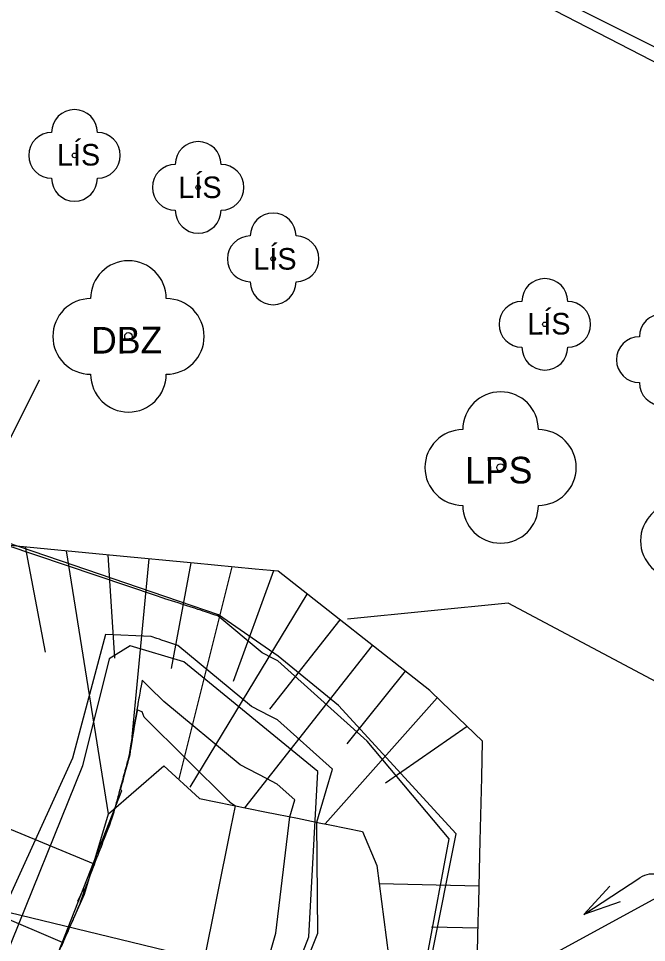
# Model space of a CAD drawing. Extents: x -564037 to -563722, y -1163561 to -1163412.
# Drawn here: x -563889.78 to -563870.9, y -1163493.12 to -1163465.35 of the extents above; entities that cross this region are included whole.
import ezdxf

# ---------------------------------------------------------------- set-up
doc = ezdxf.new("R2010")
doc.units = 0
for name, color, linetype in [('5', 7, 'Continuous'), ('Default', 7, 'Continuous'), ('Line', 7, 'Continuous'), ('Obvod PU', 7, 'Continuous'), ('podélný profil', 7, 'Continuous'), ('Vrstva 1', 7, 'Continuous'), ('Vrstva 2', 7, 'Continuous')]:
    doc.layers.add(name, color=color, linetype=linetype)

msp = doc.modelspace()

# ---------------------------------------------------------------- linework, layer by layer
msp.add_line((-563887.997, -1163491.869), (-563887.811, -1163491.492))
for points in [[(-563982.839, -1163488.47), (-563983.409, -1163491.846), (-563990.891, -1163500.051), (-563993.495, -1163501.54), (-564001.695, -1163505.76), (-564021.072, -1163514.028), (-564021.939, -1163519.359), (-564028.021, -1163535.92), (-563982.332, -1163543.556), (-563870.708, -1163549.442), (-563829.278, -1163493.346), (-563857.264, -1163473.56), (-563873.956, -1163464.96), (-563885.354, -1163462.845), (-563964.187, -1163417.135), (-563977.612, -1163460.096), (-563977.509, -1163470.055), (-563981.031, -1163479.642), (-563982.839, -1163488.47)], [(-563890.966, -1163479.851), (-563889.152, -1163476.21), (-563889.15, -1163476.207)], [(-563878.137, -1163496.97), (-563876.837, -1163490), (-563879.296, -1163487.066), (-563881.987, -1163484.651), (-563882.119, -1163484.582), (-563882.455, -1163484.408), (-563883.788, -1163483.304), (-563883.864, -1163483.279), (-563884.159, -1163483.181), (-563884.226, -1163483.159), (-563884.302, -1163483.134), (-563884.34, -1163483.121), (-563884.386, -1163483.106), (-563884.482, -1163483.074), (-563884.592, -1163483.038), (-563884.718, -1163482.996), (-563884.865, -1163482.947), (-563884.978, -1163482.91), (-563885.376, -1163482.786), (-563885.4, -1163482.777), (-563885.486, -1163482.747), (-563885.596, -1163482.707), (-563890.151, -1163481.173)], [(-563866.782, -1163487.32), (-563875.054, -1163482.917), (-563879.887, -1163483.398)], [(-563882.19, -1163496.364), (-563880.778, -1163492.835), (-563880.808, -1163489.502), (-563880.527, -1163488.546), (-563880.34, -1163487.91), (-563881.995, -1163486.424), (-563882.215, -1163486.31), (-563882.772, -1163486.021), (-563884.984, -1163484.19), (-563885.111, -1163484.148), (-563885.233, -1163484.108), (-563885.348, -1163484.069), (-563885.478, -1163484.026), (-563885.544, -1163484.004), (-563885.623, -1163483.978), (-563885.788, -1163483.923), (-563887.164, -1163483.863), (-563888.153, -1163487.579), (-563890.867, -1163493.518)], [(-563883.008, -1163496.199), (-563882.04, -1163492.836), (-563881.625, -1163489.337), (-563881.476, -1163488.829), (-563882.005, -1163488.354), (-563882.32, -1163488.191), (-563883.117, -1163487.777), (-563885.412, -1163485.878), (-563885.848, -1163485.443), (-563886.064, -1163485.228), (-563886.076, -1163485.297), (-563886.076, -1163485.299), (-563886.085, -1163485.349), (-563886.086, -1163485.357), (-563886.119, -1163485.544), (-563886.123, -1163485.565), (-563886.154, -1163485.739), (-563886.159, -1163485.771), (-563886.188, -1163485.934), (-563886.195, -1163485.977), (-563886.222, -1163486.129), (-563886.225, -1163486.143), (-563886.233, -1163486.193), (-563886.255, -1163486.313), (-563886.255, -1163486.317), (-563886.275, -1163486.425), (-563886.283, -1163486.475), (-563886.288, -1163486.503), (-563886.291, -1163486.518), (-563886.312, -1163486.636), (-563886.324, -1163486.708), (-563886.339, -1163486.796), (-563886.352, -1163486.873), (-563886.356, -1163486.898), (-563886.367, -1163486.965), (-563886.38, -1163487.043), (-563886.387, -1163487.088), (-563886.417, -1163487.278), (-563886.42, -1163487.295), (-563886.422, -1163487.306), (-563886.427, -1163487.341), (-563886.437, -1163487.403), (-563886.447, -1163487.469), (-563886.478, -1163487.59), (-563886.495, -1163487.654), (-563886.499, -1163487.669), (-563886.517, -1163487.732), (-563886.546, -1163487.835), (-563886.579, -1163487.957), (-563886.595, -1163488.016), (-563886.628, -1163488.14), (-563886.644, -1163488.198), (-563886.656, -1163488.242), (-563886.661, -1163488.262), (-563886.683, -1163488.343), (-563886.693, -1163488.379), (-563886.719, -1163488.477), (-563886.73, -1163488.518), (-563886.738, -1163488.548), (-563886.742, -1163488.561), (-563886.761, -1163488.632), (-563886.775, -1163488.684), (-563886.791, -1163488.742), (-563886.826, -1163488.871), (-563886.84, -1163488.923), (-563886.875, -1163489.052), (-563886.889, -1163489.104), (-563886.908, -1163489.177), (-563886.916, -1163489.206), (-563886.923, -1163489.229), (-563886.938, -1163489.287), (-563886.982, -1163489.414), (-563887, -1163489.464), (-563887.048, -1163489.589), (-563887.067, -1163489.639), (-563887.115, -1163489.763), (-563887.134, -1163489.813), (-563887.183, -1163489.938), (-563887.201, -1163489.987), (-563887.239, -1163490.083), (-563887.253, -1163490.12), (-563887.264, -1163490.149), (-563887.268, -1163490.16), (-563887.317, -1163490.287), (-563887.335, -1163490.334), (-563887.372, -1163490.43), (-563887.386, -1163490.466), (-563887.398, -1163490.497), (-563887.402, -1163490.508), (-563887.451, -1163490.636), (-563887.469, -1163490.682), (-563887.518, -1163490.811), (-563887.535, -1163490.856), (-563887.585, -1163490.985), (-563887.602, -1163491.03), (-563887.651, -1163491.16), (-563887.668, -1163491.204), (-563887.718, -1163491.335), (-563887.734, -1163491.379), (-563887.784, -1163491.509), (-563887.801, -1163491.552), (-563887.849, -1163491.684), (-563887.865, -1163491.727), (-563887.879, -1163491.77), (-563887.924, -1163491.903), (-563887.927, -1163491.911), (-563887.935, -1163491.936), (-563887.948, -1163491.97), (-563887.99, -1163492.08), (-563888.048, -1163492.212), (-563888.066, -1163492.252), (-563888.109, -1163492.35), (-563888.121, -1163492.379), (-563888.136, -1163492.413), (-563888.14, -1163492.423), (-563888.199, -1163492.556), (-563888.215, -1163492.594), (-563888.274, -1163492.728), (-563888.29, -1163492.765), (-563888.313, -1163492.818), (-563888.319, -1163492.832), (-563888.355, -1163492.915), (-563888.364, -1163492.937), (-563888.424, -1163493.073), (-563888.439, -1163493.108), (-563888.499, -1163493.245)], [(-563884.64, -1163495.87), (-563883.396, -1163489.693), (-563883.258, -1163489.008), (-563883.35, -1163488.961), (-563883.403, -1163488.916), (-563883.413, -1163488.906), (-563883.424, -1163488.896), (-563883.429, -1163488.891), (-563883.454, -1163488.866), (-563886.003, -1163486.346), (-563886.061, -1163486.188), (-563886.092, -1163486.174), (-563886.139, -1163486.152), (-563886.207, -1163486.12), (-563886.209, -1163486.131), (-563886.213, -1163486.15), (-563886.213, -1163486.152), (-563886.242, -1163486.315), (-563886.242, -1163486.316), (-563886.269, -1163486.463), (-563886.271, -1163486.477), (-563886.278, -1163486.515), (-563886.279, -1163486.52), (-563886.307, -1163486.681), (-563886.312, -1163486.71), (-563886.334, -1163486.831), (-563886.339, -1163486.866), (-563886.345, -1163486.9), (-563886.36, -1163486.992), (-563886.366, -1163487.027), (-563886.376, -1163487.09), (-563886.4, -1163487.252), (-563886.405, -1163487.28), (-563886.409, -1163487.304), (-563886.409, -1163487.308), (-563886.417, -1163487.357), (-563886.421, -1163487.379), (-563886.435, -1163487.472), (-563886.478, -1163487.642), (-563886.482, -1163487.657), (-563886.488, -1163487.679), (-563886.492, -1163487.693), (-563886.532, -1163487.838), (-563886.579, -1163488.011), (-563886.581, -1163488.02), (-563886.629, -1163488.196), (-563886.63, -1163488.201), (-563886.647, -1163488.265), (-563886.647, -1163488.266), (-563886.678, -1163488.381), (-563886.679, -1163488.383), (-563886.713, -1163488.512), (-563886.706, -1163488.522), (-563886.68, -1163488.561), (-563886.68, -1163488.562), (-563886.68, -1163488.562), (-563886.679, -1163488.563), (-563889.53, -1163495.82)], [(-563889.53, -1163495.82), (-563888.841, -1163493.998), (-563888.841, -1163493.998), (-563888.841, -1163493.998), (-563887.797, -1163491.659), (-563887.07, -1163489.251), (-563885.406, -1163487.811), (-563884.336, -1163488.791), (-563884.336, -1163488.791), (-563884.336, -1163488.791), (-563883.356, -1163488.989), (-563882.375, -1163489.186), (-563882.009, -1163489.26), (-563881.395, -1163489.384), (-563880.687, -1163489.526), (-563880.415, -1163489.581), (-563879.434, -1163489.779), (-563879.009, -1163490.8), (-563878.655, -1163493.506)]]:
    msp.add_lwpolyline(points)
for points in [[(-563900.324, -1163505.882), (-563892.678, -1163503.006), (-563888.735, -1163501.906), (-563886.271, -1163502.018), (-563883.536, -1163500.684), (-563878.095, -1163497.234), (-563876.621, -1163489.849), (-563880.163, -1163485.998), (-563881.977, -1163484.515), (-563883.765, -1163483.269), (-563890.133, -1163481.092), (-563891.974, -1163485.382), (-563895.143, -1163493.304), (-563898.704, -1163502.458), (-563900.439, -1163505.855)], [(-563887.058, -1163484.593), (-563887.855, -1163487.81), (-563890.21, -1163493.633), (-563891.581, -1163498.253), (-563891.461, -1163499.576), (-563890.275, -1163499.82), (-563886.599, -1163499.649), (-563882.84, -1163497.558), (-563881.049, -1163492.941), (-563880.784, -1163487.979), (-563884.81, -1163484.679), (-563886.418, -1163484.198)]]:
    msp.add_lwpolyline(points, close=True)
at = {"layer": '5'}
for p, q in [((-563897.15, -1163506.247), (-563862.812, -1163487.513)), ((-563904.23, -1163488.796), (-563873.359, -1163496.24))]:
    msp.add_line(p, q, dxfattribs=at)
at = {"layer": 'Default'}
msp.add_lwpolyline([(-563875.979, -1163493.391), (-563875.957, -1163492.484), (-563875.943, -1163491.921), (-563875.909, -1163490.489), (-563875.899, -1163490.06), (-563875.853, -1163488.158), (-563875.827, -1163487.061), (-563877.051, -1163485.894), (-563877.417, -1163485.546), (-563881.974, -1163481.961), (-563882.667, -1163481.894), (-563884.497, -1163481.718), (-563886.832, -1163481.493), (-563890.151, -1163481.173)], dxfattribs=at)
at = {"layer": 'Line'}
for p, q in [((-563889.579, -1163481.228), (-563888.976, -1163484.391)), ((-563887.07, -1163489.251), (-563888.335, -1163481.348)), ((-563887.091, -1163481.468), (-563886.894, -1163484.572)), ((-563886.362, -1163486.934), (-563885.847, -1163481.588)), ((-563884.602, -1163481.708), (-563885.193, -1163484.881)), ((-563884.948, -1163488.198), (-563883.358, -1163481.827)), ((-563882.114, -1163481.947), (-563883.329, -1163485.273)), ((-563884.614, -1163488.443), (-563881.102, -1163482.646)), ((-563880.12, -1163483.419), (-563882.231, -1163486.103)), ((-563882.972, -1163489.066), (-563879.137, -1163484.192)), ((-563878.155, -1163484.965), (-563879.913, -1163487.147)), ((-563880.557, -1163489.552), (-563877.192, -1163485.76)), ((-563876.287, -1163486.623), (-563878.747, -1163488.324)), ((-563892.197, -1163488.809), (-563887.537, -1163490.746)), ((-563893.169, -1163491.112), (-563888.462, -1163493.101)), ((-563875.931, -1163491.424), (-563878.937, -1163491.352)), ((-563877.367, -1163492.64), (-563875.961, -1163492.674))]:
    msp.add_line(p, q, dxfattribs=at)
at = {"layer": 'Obvod PU'}
msp.add_lwpolyline([(-563885.14, -1163462.32), (-563874.2, -1163464.42), (-563869.21, -1163466.93)], dxfattribs=at)
at = {"layer": 'podélný profil'}
for points in [[(-563872.789, -1163492.275), (-563871.102, -1163491.17)], [(-563871.691, -1163491.893), (-563872.789, -1163492.275), (-563872, -1163491.421)]]:
    msp.add_lwpolyline(points, dxfattribs=at)
msp.add_arc((-563870.731, -1163491.737), 0.677, 71.5291, 123.2236, dxfattribs=at)
at = {"layer": 'Vrstva 2'}
for centre, radius in [((-563888.095, -1163469.463), 0.0688), ((-563884.377, -1163470.424), 0.0688), ((-563882.123, -1163472.573), 0.0688), ((-563873.957, -1163474.54), 0.0688), ((-563886.473, -1163474.903), 0.114), ((-563886.473, -1163474.903), 0.114), ((-563875.286, -1163478.842), 0.114)]:
    msp.add_circle(centre, radius, dxfattribs=at)
for centre, radius, start, end in [((-563888.095, -1163468.775), 0.688, 0, 180), ((-563888.783, -1163469.463), 0.688, 90, 270), ((-563887.407, -1163469.463), 0.688, 270, 90), ((-563884.377, -1163469.736), 0.688, 0, 180), ((-563885.065, -1163470.424), 0.688, 90, 270), ((-563883.689, -1163470.424), 0.688, 270, 90), ((-563888.095, -1163470.151), 0.688, 180, 0), ((-563884.377, -1163471.112), 0.688, 180, 0), ((-563882.123, -1163471.885), 0.688, 0, 180), ((-563882.811, -1163472.573), 0.688, 90, 270), ((-563881.435, -1163472.573), 0.688, 270, 90), ((-563886.473, -1163473.765), 1.137, 0, 180), ((-563886.473, -1163473.765), 1.137, 0, 180), ((-563882.123, -1163473.261), 0.688, 180, 0), ((-563873.957, -1163473.852), 0.688, 0, 180), ((-563887.61, -1163474.903), 1.137, 90, 270), ((-563887.61, -1163474.903), 1.137, 90, 270), ((-563885.335, -1163474.903), 1.137, 270, 90), ((-563885.335, -1163474.903), 1.137, 270, 90), ((-563874.645, -1163474.54), 0.688, 90, 270), ((-563873.269, -1163474.54), 0.688, 270, 90), ((-563870.427, -1163474.916), 0.688, 0, 180), ((-563871.115, -1163475.604), 0.688, 90, 270), ((-563873.957, -1163475.228), 0.688, 180, 0), ((-563886.473, -1163476.04), 1.137, 180, 0), ((-563886.473, -1163476.04), 1.137, 180, 0), ((-563870.427, -1163476.292), 0.688, 180, 0), ((-563875.286, -1163477.705), 1.137, 0, 180), ((-563876.423, -1163478.842), 1.137, 90, 270), ((-563874.149, -1163478.842), 1.137, 270, 90), ((-563875.286, -1163479.979), 1.137, 180, 0), ((-563869.942, -1163481.044), 1.137, 90, 270), ((-563869.942, -1163481.044), 1.137, 90, 270)]:
    msp.add_arc(centre, radius, start, end, dxfattribs=at)

# ---------------------------------------------------------------- texts
at = {"layer": 'Vrstva 1'}
for s, height, p in [('LÍS', 0.648, (-563888.623, -1163469.771)), ('LÍS', 0.648, (-563884.973, -1163470.749)), ('LÍS', 0.648, (-563882.719, -1163472.899)), ('LÍS', 0.648, (-563874.484, -1163474.848)), ('DBZ', 0.8, (-563887.596, -1163475.419)), ('LPS', 0.8, (-563876.351, -1163479.325))]:
    msp.add_text(s, height=height, rotation=0.1546, dxfattribs=at).set_placement(p)

doc.saveas('drawing.dxf')
